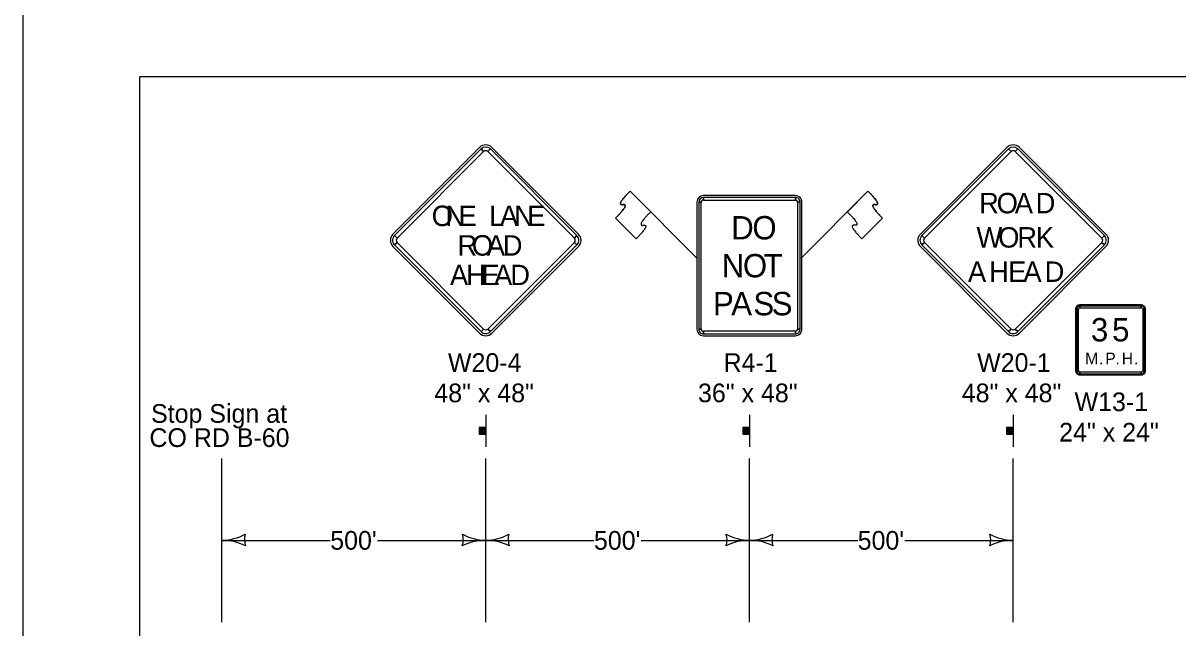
# Model space of a CAD drawing. Extents: x -2134934 to -2122394, y -2139046 to -2137036.
# Drawn here: x -2125529 to -2124540, y -2138559 to -2138041 of the extents above; entities that cross this region are included whole.
import ezdxf

# ---------------------------------------------------------------- set-up
doc = ezdxf.new("R2010")
doc.units = 0
for name, color, linetype in [('Barrier', 7, 'Continuous'), ('BridgeSuperStructureExisting', 7, 'Continuous'), ('Default', 7, 'Continuous'), ('TC_Barrier', 7, 'Continuous')]:
    doc.layers.add(name, color=color, linetype=linetype)

msp = doc.modelspace()

# ---------------------------------------------------------------- linework, layer by layer
at = {"layer": 'Barrier'}
for p, q in [((-2125138.25, -2138147.46), (-2125212.49, -2138221.71)), ((-2125136.92, -2138148.79), (-2125134.71, -2138151)), ((-2125131.18, -2138151), (-2125128.97, -2138148.79)), ((-2125053.4, -2138221.71), (-2125127.64, -2138147.46)), ((-2124686.17, -2138147.46), (-2124760.42, -2138221.71)), ((-2124684.85, -2138148.79), (-2124682.64, -2138151)), ((-2124679.1, -2138151), (-2124676.89, -2138148.79)), ((-2124601.32, -2138221.71), (-2124675.57, -2138147.46)), ((-2124951.91, -2138242.27), (-2125009.24, -2138184.97)), ((-2125009.24, -2138184.97), (-2124991.55, -2138202.65)), ((-2124862.62, -2138242.27), (-2124805.3, -2138184.96)), ((-2124805.3, -2138184.96), (-2124822.98, -2138202.64)), ((-2124951.91, -2138194.38), (-2124951.91, -2138303.13)), ((-2124950.35, -2138194.38), (-2124948.16, -2138194.38)), ((-2124867.53, -2138188.76), (-2124946.28, -2138188.76)), ((-2124946.28, -2138192.51), (-2124946.28, -2138190.32)), ((-2124867.53, -2138190.32), (-2124867.53, -2138192.51)), ((-2124865.66, -2138194.38), (-2124863.47, -2138194.38)), ((-2124861.91, -2138303.13), (-2124861.91, -2138194.38)), ((-2125003.93, -2138225.64), (-2125021.61, -2138207.97)), ((-2124810.6, -2138225.63), (-2124792.92, -2138207.95)), ((-2125208.96, -2138225.24), (-2125211.17, -2138223.03)), ((-2125054.72, -2138223.03), (-2125056.93, -2138225.24)), ((-2124756.89, -2138225.24), (-2124759.09, -2138223.03)), ((-2124602.65, -2138223.03), (-2124604.86, -2138225.24)), ((-2125212.49, -2138232.31), (-2125138.25, -2138306.56)), ((-2125211.17, -2138230.99), (-2125208.96, -2138228.78)), ((-2125127.64, -2138306.56), (-2125053.4, -2138232.31)), ((-2125056.93, -2138228.78), (-2125054.72, -2138230.99)), ((-2124760.42, -2138232.31), (-2124686.17, -2138306.56)), ((-2124759.09, -2138230.99), (-2124756.89, -2138228.78)), ((-2124675.57, -2138306.56), (-2124601.32, -2138232.31)), ((-2124604.86, -2138228.78), (-2124602.65, -2138230.99)), ((-2124571.1, -2138282.4), (-2124623.6, -2138282.4)), ((-2124623.6, -2138284.9), (-2124623.6, -2138283.34)), ((-2124571.1, -2138283.34), (-2124571.1, -2138284.9)), ((-2124627.35, -2138286.15), (-2124627.35, -2138338.65)), ((-2124626.41, -2138286.15), (-2124624.85, -2138286.15)), ((-2124569.85, -2138286.15), (-2124568.29, -2138286.15)), ((-2124567.35, -2138338.65), (-2124567.35, -2138286.15)), ((-2125134.71, -2138303.03), (-2125136.92, -2138305.24)), ((-2125128.97, -2138305.24), (-2125131.18, -2138303.03)), ((-2124948.16, -2138303.13), (-2124950.35, -2138303.13)), ((-2124863.47, -2138303.13), (-2124865.66, -2138303.13)), ((-2124682.64, -2138303.03), (-2124684.85, -2138305.24)), ((-2124676.89, -2138305.24), (-2124679.1, -2138303.03)), ((-2124946.28, -2138307.2), (-2124946.28, -2138305.01)), ((-2124946.28, -2138308.76), (-2124867.53, -2138308.76)), ((-2124867.53, -2138305.01), (-2124867.53, -2138307.2)), ((-2124624.85, -2138338.65), (-2124626.41, -2138338.65)), ((-2124623.6, -2138341.46), (-2124623.6, -2138339.9)), ((-2124623.6, -2138342.4), (-2124571.1, -2138342.4)), ((-2124571.1, -2138339.9), (-2124571.1, -2138341.46)), ((-2124568.29, -2138338.65), (-2124569.85, -2138338.65))]:
    msp.add_line(p, q, dxfattribs=at)
for points in [[(-2125429.46, -2138086.59), (-2124308.22, -2138086.59), (-2124308.22, -2138937.23), (-2125429.46, -2138937.23)], [(-2125136.92, -2138148.79), (-2125211.17, -2138223.03), (-2125208.96, -2138225.24), (-2125134.71, -2138151), (-2125136.92, -2138148.79)], [(-2125054.72, -2138223.03), (-2125128.97, -2138148.79), (-2125131.18, -2138151), (-2125056.93, -2138225.24), (-2125054.72, -2138223.03)], [(-2124684.85, -2138148.79), (-2124759.09, -2138223.03), (-2124756.89, -2138225.24), (-2124682.64, -2138151), (-2124684.85, -2138148.79)], [(-2124602.65, -2138223.03), (-2124676.89, -2138148.79), (-2124679.1, -2138151), (-2124604.86, -2138225.24), (-2124602.65, -2138223.03)], [(-2124950.35, -2138194.38), (-2124950.35, -2138303.13), (-2124948.16, -2138303.13), (-2124948.16, -2138194.38), (-2124950.35, -2138194.38)], [(-2124867.53, -2138190.32), (-2124946.28, -2138190.32), (-2124946.28, -2138192.51), (-2124867.53, -2138192.51), (-2124867.53, -2138190.32)], [(-2124863.47, -2138303.13), (-2124863.47, -2138194.38), (-2124865.66, -2138194.38), (-2124865.66, -2138303.13), (-2124863.47, -2138303.13)], [(-2125211.17, -2138230.99), (-2125136.92, -2138305.24), (-2125134.71, -2138303.03), (-2125208.96, -2138228.78), (-2125211.17, -2138230.99)], [(-2125128.97, -2138305.24), (-2125054.72, -2138230.99), (-2125056.93, -2138228.78), (-2125131.18, -2138303.03), (-2125128.97, -2138305.24)], [(-2124759.09, -2138230.99), (-2124684.85, -2138305.24), (-2124682.64, -2138303.03), (-2124756.89, -2138228.78), (-2124759.09, -2138230.99)], [(-2124676.89, -2138305.24), (-2124602.65, -2138230.99), (-2124604.86, -2138228.78), (-2124679.1, -2138303.03), (-2124676.89, -2138305.24)], [(-2124571.1, -2138283.34), (-2124623.6, -2138283.34), (-2124623.6, -2138284.9), (-2124571.1, -2138284.9), (-2124571.1, -2138283.34)], [(-2124626.41, -2138286.15), (-2124626.41, -2138338.65), (-2124624.85, -2138338.65), (-2124624.85, -2138286.15), (-2124626.41, -2138286.15)], [(-2124568.29, -2138338.65), (-2124568.29, -2138286.15), (-2124569.85, -2138286.15), (-2124569.85, -2138338.65), (-2124568.29, -2138338.65)], [(-2124946.28, -2138307.2), (-2124867.53, -2138307.2), (-2124867.53, -2138305.01), (-2124946.28, -2138305.01), (-2124946.28, -2138307.2)], [(-2124623.6, -2138341.46), (-2124571.1, -2138341.46), (-2124571.1, -2138339.9), (-2124623.6, -2138339.9), (-2124623.6, -2138341.46)]]:
    msp.add_lwpolyline(points, close=True, dxfattribs=at)
for centre, radius, start, end in [((-2125132.94, -2138152.77), 7.5, 44.99999, 134.99974), ((-2124680.87, -2138152.77), 7.5, 44.99999, 134.99974), ((-2125132.94, -2138152.77), 5.62, 44.99999, 134.99974), ((-2125132.94, -2138152.77), 2.5, 44.99999, 134.99974), ((-2124680.87, -2138152.77), 5.62, 44.99999, 134.99974), ((-2124680.87, -2138152.77), 2.5, 44.99999, 134.99974), ((-2124946.28, -2138194.38), 5.62, 90.00021, 179.99985), ((-2124946.28, -2138194.38), 4.06, 90.00021, 179.99985), ((-2124946.28, -2138194.38), 1.87, 90.00021, 179.99985), ((-2124867.53, -2138194.38), 5.62, 0, 90.00021), ((-2124867.53, -2138194.38), 4.06, 0, 90.00021), ((-2124867.53, -2138194.38), 1.87, 0, 90.00021), ((-2125207.19, -2138227.01), 7.5, 134.99974, 224.99995), ((-2125207.19, -2138227.01), 5.62, 134.99974, 224.99995), ((-2125058.7, -2138227.01), 5.62, 315.00016, 44.9998), ((-2125058.7, -2138227.01), 7.5, 315.00016, 44.9998), ((-2124755.12, -2138227.01), 7.5, 134.99974, 224.99995), ((-2124755.12, -2138227.01), 5.62, 134.99974, 224.99995), ((-2124606.63, -2138227.01), 5.62, 315.00016, 44.9998), ((-2124606.63, -2138227.01), 7.5, 315.00016, 44.9998), ((-2125207.19, -2138227.01), 2.5, 134.99974, 224.99995), ((-2125058.7, -2138227.01), 2.5, 315.00016, 44.9998), ((-2124755.12, -2138227.01), 2.5, 134.99974, 224.99995), ((-2124606.63, -2138227.01), 2.5, 315.00016, 44.9998), ((-2124623.6, -2138286.15), 3.75, 90.00021, 179.99985), ((-2124623.6, -2138286.15), 2.81, 90.00021, 179.99985), ((-2124571.1, -2138286.15), 3.75, 0, 90.00021), ((-2124571.1, -2138286.15), 2.81, 0, 90.00021), ((-2124623.6, -2138286.15), 1.25, 90.00021, 179.99985), ((-2124571.1, -2138286.15), 1.25, 0, 90.00021), ((-2125132.94, -2138301.26), 2.5, 224.99995, 315.00016), ((-2124946.28, -2138303.13), 5.62, 179.99985, 270.00006), ((-2124946.28, -2138303.13), 4.06, 179.99985, 270.00006), ((-2124946.28, -2138303.13), 1.87, 179.99985, 270.00006), ((-2124867.53, -2138303.13), 5.62, 270.00006, 0.00027), ((-2124867.53, -2138303.13), 4.06, 270.00006, 0.00027), ((-2124867.53, -2138303.13), 1.87, 270.00006, 0.00027), ((-2124680.87, -2138301.26), 2.5, 224.99995, 315.00016), ((-2125132.94, -2138301.26), 7.5, 224.99995, 315.00016), ((-2125132.94, -2138301.26), 5.62, 224.99995, 315.00016), ((-2124680.87, -2138301.26), 7.5, 224.99995, 315.00016), ((-2124680.87, -2138301.26), 5.62, 224.99995, 315.00016), ((-2124623.6, -2138338.65), 3.75, 179.99985, 270.00006), ((-2124623.6, -2138338.65), 2.81, 179.99985, 270.00006), ((-2124623.6, -2138338.65), 1.25, 179.99985, 270.00006), ((-2124571.1, -2138338.65), 3.75, 270.00006, 0.00027), ((-2124571.1, -2138338.65), 2.81, 270.00006, 0.00027), ((-2124571.1, -2138338.65), 1.25, 270.00006, 0.00027)]:
    msp.add_arc(centre, radius, start, end, dxfattribs=at)
for points in [[(-2125021.61, -2138207.97), (-2125009.24, -2138195.59), (-2125021.62, -2138197.36), (-2125009.24, -2138184.97)], [(-2124792.92, -2138207.95), (-2124805.3, -2138195.57), (-2124792.92, -2138197.34), (-2124805.3, -2138184.96)], [(-2124991.55, -2138202.65), (-2125003.93, -2138215.04), (-2124991.56, -2138213.26), (-2125003.93, -2138225.64)], [(-2124822.98, -2138202.64), (-2124810.6, -2138215.02), (-2124822.97, -2138213.25), (-2124810.6, -2138225.63)]]:
    msp.add_open_spline(points, degree=2, dxfattribs=at)
at = {"layer": 'BridgeSuperStructureExisting'}
for p, q in [((-2125132.94, -2138376.58), (-2125132.94, -2138404.08)), ((-2124906.91, -2138376.58), (-2124906.91, -2138404.08)), ((-2124680.87, -2138376.58), (-2124680.87, -2138404.08)), ((-2125138.27, -2138387.44), (-2125138.27, -2138393.03)), ((-2125137.95, -2138393.03), (-2125137.95, -2138387.44)), ((-2125137.73, -2138387.44), (-2125137.73, -2138393.03)), ((-2125137.41, -2138393.03), (-2125137.41, -2138387.44)), ((-2125137.18, -2138387.44), (-2125137.2, -2138393.03)), ((-2125136.77, -2138393.03), (-2125136.75, -2138387.44)), ((-2125136.55, -2138387.44), (-2125136.55, -2138393.03)), ((-2125136.11, -2138393.03), (-2125136.11, -2138387.44)), ((-2125135.74, -2138387.44), (-2125135.74, -2138393.03)), ((-2125135.42, -2138393.03), (-2125135.4, -2138387.44)), ((-2125135.2, -2138387.44), (-2125135.2, -2138393.03)), ((-2125134.93, -2138393.03), (-2125134.93, -2138387.44)), ((-2125134.6, -2138387.44), (-2125134.6, -2138393.03)), ((-2125134.39, -2138393.03), (-2125134.39, -2138387.44)), ((-2125134.16, -2138387.44), (-2125134.16, -2138393.03)), ((-2125133.9, -2138393.03), (-2125133.9, -2138387.44)), ((-2125133.64, -2138387.44), (-2125133.64, -2138393.03)), ((-2125133.36, -2138393.03), (-2125133.36, -2138387.44)), ((-2124912.23, -2138387.44), (-2124912.23, -2138393.03)), ((-2124911.92, -2138393.03), (-2124911.92, -2138387.44)), ((-2124911.69, -2138387.44), (-2124911.69, -2138393.03)), ((-2124911.37, -2138393.03), (-2124911.37, -2138387.44)), ((-2124911.15, -2138387.44), (-2124911.17, -2138393.03)), ((-2124910.73, -2138393.03), (-2124910.72, -2138387.44)), ((-2124910.51, -2138387.44), (-2124910.51, -2138393.03)), ((-2124910.08, -2138393.03), (-2124910.08, -2138387.44)), ((-2124909.7, -2138387.44), (-2124909.7, -2138393.03)), ((-2124909.38, -2138393.03), (-2124909.37, -2138387.44)), ((-2124909.16, -2138387.44), (-2124909.16, -2138393.03)), ((-2124908.9, -2138393.03), (-2124908.9, -2138387.44)), ((-2124908.56, -2138387.44), (-2124908.56, -2138393.03)), ((-2124908.35, -2138393.03), (-2124908.35, -2138387.44)), ((-2124908.13, -2138387.44), (-2124908.13, -2138393.03)), ((-2124907.87, -2138393.03), (-2124907.87, -2138387.44)), ((-2124907.6, -2138387.44), (-2124907.6, -2138393.03)), ((-2124907.32, -2138393.03), (-2124907.32, -2138387.44)), ((-2124686.2, -2138387.44), (-2124686.2, -2138393.03)), ((-2124685.88, -2138393.03), (-2124685.88, -2138387.44)), ((-2124685.65, -2138387.44), (-2124685.65, -2138393.03)), ((-2124685.34, -2138393.03), (-2124685.34, -2138387.44)), ((-2124685.11, -2138387.44), (-2124685.13, -2138393.03)), ((-2124684.7, -2138393.03), (-2124684.68, -2138387.44)), ((-2124684.47, -2138387.44), (-2124684.47, -2138393.03)), ((-2124684.04, -2138393.03), (-2124684.04, -2138387.44)), ((-2124683.67, -2138387.44), (-2124683.67, -2138393.03)), ((-2124683.35, -2138393.03), (-2124683.33, -2138387.44)), ((-2124683.12, -2138387.44), (-2124683.12, -2138393.03)), ((-2124682.86, -2138393.03), (-2124682.86, -2138387.44)), ((-2124682.52, -2138387.44), (-2124682.52, -2138393.03)), ((-2124682.32, -2138393.03), (-2124682.32, -2138387.44)), ((-2124682.09, -2138387.44), (-2124682.09, -2138393.03)), ((-2124681.83, -2138393.03), (-2124681.83, -2138387.44)), ((-2124681.57, -2138387.44), (-2124681.57, -2138393.03)), ((-2124681.29, -2138393.03), (-2124681.29, -2138387.44)), ((-2125358.98, -2138554.08), (-2125358.98, -2138414.08)), ((-2125132.94, -2138554.08), (-2125132.94, -2138414.08)), ((-2124906.91, -2138554.08), (-2124906.91, -2138414.08)), ((-2124680.87, -2138554.08), (-2124680.87, -2138414.08)), ((-2125358.98, -2138484.08), (-2125266.21, -2138484.08)), ((-2125225.71, -2138484.08), (-2125132.94, -2138484.08)), ((-2125132.94, -2138484.08), (-2125040.18, -2138484.08)), ((-2124999.68, -2138484.08), (-2124906.91, -2138484.08)), ((-2124906.91, -2138484.08), (-2124814.14, -2138484.08)), ((-2124773.64, -2138484.08), (-2124680.87, -2138484.08))]:
    msp.add_line(p, q, dxfattribs=at)
for points in [[(-2125133.04, -2138393.03), (-2125133.04, -2138387.4), (-2125138.66, -2138387.4), (-2125138.66, -2138393.03)], [(-2124907, -2138393.03), (-2124907, -2138387.4), (-2124912.63, -2138387.4), (-2124912.63, -2138393.03)], [(-2124680.97, -2138393.03), (-2124680.97, -2138387.4), (-2124686.59, -2138387.4), (-2124686.59, -2138393.03)]]:
    msp.add_lwpolyline(points, close=True, dxfattribs=at)
for centre, radius, start, end in [((-2125359.74, -2138441.59), 42.5, 271.0176, 299.07249), ((-2125323.36, -2138483.46), 16.42, 163.26665, 198.73335), ((-2125168.56, -2138483.46), 16.42, 341.26665, 16.73335), ((-2125132.19, -2138441.59), 42.5, 240.92751, 268.9824), ((-2125133.7, -2138441.59), 42.5, 271.0176, 299.07249), ((-2125097.33, -2138483.46), 16.42, 163.26665, 198.73335), ((-2124942.53, -2138483.46), 16.42, 341.26665, 16.73335), ((-2124906.15, -2138441.59), 42.5, 240.92751, 268.9824), ((-2124907.66, -2138441.59), 42.5, 271.0176, 299.07249), ((-2124871.29, -2138483.46), 16.42, 163.26665, 198.73335), ((-2124716.49, -2138483.46), 16.42, 341.26665, 16.73335), ((-2124680.12, -2138441.59), 42.5, 240.92751, 268.9824), ((-2125358.25, -2138526.57), 42.5, 62.92751, 90.9824), ((-2125133.67, -2138526.57), 42.5, 89.0176, 117.07249), ((-2125132.22, -2138526.57), 42.5, 62.92751, 90.9824), ((-2124907.64, -2138526.57), 42.5, 89.0176, 117.07249), ((-2124906.18, -2138526.57), 42.5, 62.92751, 90.9824), ((-2124681.6, -2138526.57), 42.5, 89.0176, 117.07249)]:
    msp.add_arc(centre, radius, start, end, dxfattribs=at)
at = {"layer": 'Default'}
msp.add_lwpolyline([(-2125529.46, -2137035.95), (-2122394.47, -2137035.95), (-2122394.47, -2139045.94), (-2125529.46, -2139045.94)], close=True, dxfattribs=at)
at = {"layer": 'TC_Barrier'}
for p, q in [((-2125021.61, -2138207.97), (-2125003.93, -2138225.64)), ((-2124792.92, -2138207.95), (-2124810.6, -2138225.63))]:
    msp.add_line(p, q, dxfattribs=at)
for points in [[(-2125009.24, -2138184.97), (-2125021.62, -2138197.36), (-2125009.24, -2138195.59), (-2125021.61, -2138207.97)], [(-2124805.3, -2138184.96), (-2124792.92, -2138197.34), (-2124805.3, -2138195.57), (-2124792.92, -2138207.95)], [(-2124991.55, -2138202.65), (-2125003.93, -2138215.04), (-2124991.56, -2138213.26), (-2125003.93, -2138225.64)], [(-2124822.98, -2138202.64), (-2124810.6, -2138215.02), (-2124822.97, -2138213.25), (-2124810.6, -2138225.63)]]:
    msp.add_open_spline(points, degree=2, dxfattribs=at)

# ---------------------------------------------------------------- texts
at = {"layer": 'Barrier'}
for s, height, p in [('R', 17.5, (-2124710.03, -2138203.89)), ('O', 17.5, (-2124695.02, -2138203.89)), ('A', 17.5, (-2124679.47, -2138203.89)), ('D', 17.5, (-2124661.59, -2138203.89)), ('O', 17.5, (-2125179.23, -2138214.82)), ('N', 17.5, (-2125167.45, -2138214.82)), ('E', 17.5, (-2125156.23, -2138214.82)), ('L', 17.5, (-2125129.98, -2138214.82)), ('A', 17.5, (-2125120.78, -2138214.82)), ('N', 17.5, (-2125108.51, -2138214.82)), ('E', 17.5, (-2125097.28, -2138214.82)), ('D', 20, (-2124922.53, -2138226.26)), ('O', 20, (-2124904.41, -2138226.26)), ('R', 17.5, (-2125157.12, -2138240.14)), ('O', 17.5, (-2125144.83, -2138240.14)), ('A', 17.5, (-2125131.99, -2138240.14)), ('D', 17.5, (-2125118.34, -2138240.14)), ('W', 17.5, (-2124712.32, -2138233.26)), ('O', 17.5, (-2124693.72, -2138233.26)), ('R', 17.5, (-2124677.32, -2138233.26)), ('K', 17.5, (-2124661.46, -2138233.26)), ('N', 20, (-2124930.66, -2138258.76)), ('O', 20, (-2124912.53, -2138258.76)), ('T', 20, (-2124894.72, -2138258.76)), ('A', 17.5, (-2125163.56, -2138265.45)), ('H', 17.5, (-2125149.69, -2138265.45)), ('E', 17.5, (-2125136.48, -2138265.45)), ('A', 17.5, (-2125125.76, -2138265.45)), ('D', 17.5, (-2125111.9, -2138265.45)), ('A', 17.5, (-2124719.59, -2138262.64)), ('H', 17.5, (-2124701.39, -2138262.64)), ('E', 17.5, (-2124685.16, -2138262.64)), ('A', 17.5, (-2124672.11, -2138262.64)), ('D', 17.5, (-2124653.91, -2138262.64)), ('P', 20, (-2124938.17, -2138291.26)), ('A', 20, (-2124922.49, -2138291.26)), ('S', 20, (-2124903.52, -2138291.26)), ('S', 20, (-2124887.83, -2138291.26)), ('3', 20, (-2124614.2, -2138313.64)), ('5', 20, (-2124596.08, -2138313.64)), ('W20-4', 16, (-2125165.31, -2138339.76)), ('W20-1', 16, (-2124711.73, -2138339.76)), ('M', 10, (-2124619.13, -2138333.34)), ('P', 10, (-2124601.87, -2138333.34)), ('H', 10, (-2124587.75, -2138333.34)), ('R4-1', 16, (-2124929.07, -2138339.76)), ('.', 10, (-2124607.33, -2138333.34)), ('.', 10, (-2124593.21, -2138333.34)), ('.', 10, (-2124577.29, -2138333.34)), ('48" x 48"', 16, (-2125177.01, -2138365.76)), ('36" x 48"', 16, (-2124950.98, -2138365.76)), ('48" x 48"', 16, (-2124724.94, -2138365.76)), ('W13-1', 16, (-2124628.21, -2138373.4)), ('24" x 24"', 16, (-2124641.42, -2138399.4))]:
    msp.add_text(s, height=height, dxfattribs=at).set_placement(p)
at = {"layer": 'BridgeSuperStructureExisting'}
for s, p in [('Stop Sign at', (-2125419.77, -2138383.37)), ('CO RD B-60', (-2125421.17, -2138404.08)), ("500'", (-2125266.21, -2138492.08)), ("500'", (-2125040.18, -2138492.08)), ("500'", (-2124814.14, -2138492.08))]:
    msp.add_text(s, height=16, dxfattribs=at).set_placement(p)

doc.saveas('drawing.dxf')
